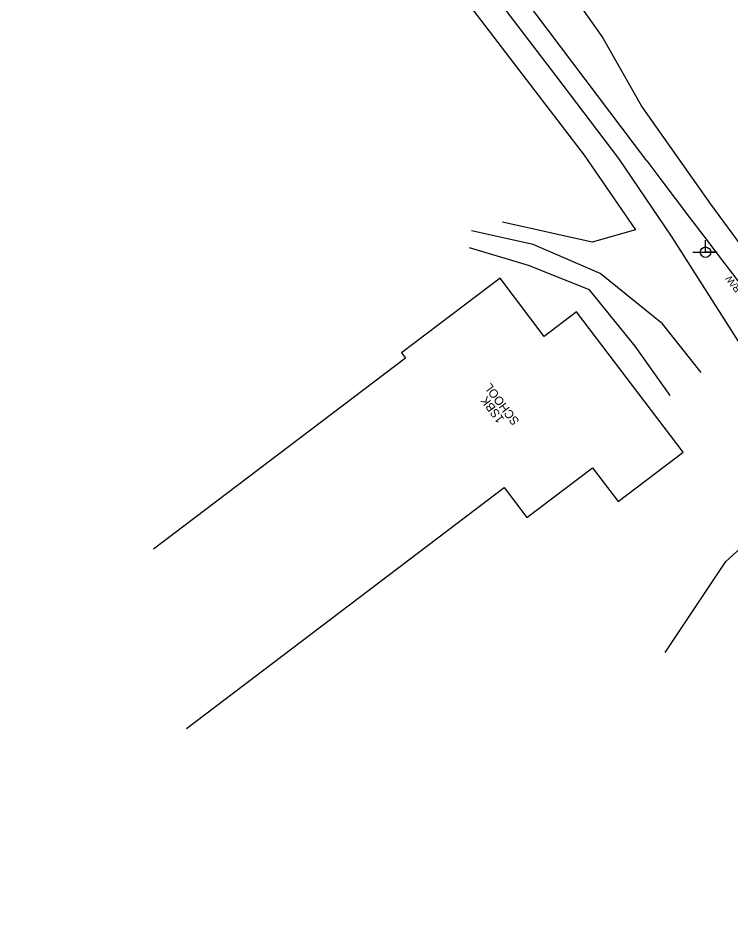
# Model space of a CAD drawing. Extents: x 1263837 to 1268319, y 770628 to 773628.
# Drawn here: x 1265545.5 to 1265875.7, y 772731.9 to 773151.3 of the extents above; entities that cross this region are included whole.
import ezdxf

# ---------------------------------------------------------------- set-up
doc = ezdxf.new("R2010")
doc.units = 0
for name, color, linetype in [('Exist Building', 7, 'Continuous'), ('Exist Building Text', 7, 'Continuous'), ('Exist Roads Soil', 7, 'Continuous'), ('Exist Utilities Gas UG Line SUE LOS B', 7, 'Continuous'), ('Exist Utilities Power Joint Use Telephone CELL', 7, 'Continuous'), ('Exist Vegetation Woods Line', 7, 'Continuous'), ('Prop Earthen Structure V Ditch Special Lateral with Rip Rap Detail CELL', 7, 'Continuous'), ('Prop Horizontal Alignment', 7, 'Continuous')]:
    doc.layers.add(name, color=color, linetype=linetype)

# ---------------------------------------------------------------- blocks, each defined once
blk = doc.blocks.new('EXIST UTILITIES POWER JOINT USE TELEPHONE')
at = {"layer": 'Exist Utilities Power Joint Use Telephone CELL'}
blk.add_line((0, 0), (0, 0), dxfattribs=at)
blk.add_lwpolyline([(-0.1188, 0), (0.108, -0.0008), (0, -0.0004), (0, 0.1125)], dxfattribs=at)
blk.add_circle((0, 0.0001), 0.049, dxfattribs=at)

msp = doc.modelspace()

# ---------------------------------------------------------------- linework, layer by layer
at = {"layer": 'Exist Building'}
for p, q in [((1265768.74, 773030.76), (1265723.08, 772996.13)), ((1265789.23, 773003.75), (1265768.74, 773030.76)), ((1265804.17, 773015.08), (1265789.23, 773003.75)), ((1265853.52, 772950.03), (1265804.17, 773015.08)), ((1265724.91, 772993.72), (1265608.21, 772905.19)), ((1265723.08, 772996.13), (1265724.91, 772993.72)), ((1265823.46, 772927.22), (1265853.52, 772950.03)), ((1265781.14, 772919.8), (1265811.57, 772942.89)), ((1265811.57, 772942.89), (1265823.46, 772927.22)), ((1265623.46, 772822.07), (1265770.61, 772933.69)), ((1265770.61, 772933.69), (1265781.14, 772919.8))]:
    msp.add_line(p, q, dxfattribs=at)
at = {"layer": 'Exist Roads Soil'}
for points in [[(1265861.85, 772986.99), (1265843.98, 773009.59), (1265815.12, 773032.96), (1265784.08, 773046.4), (1265755.54, 773052.64)], [(1265847.56, 772976.29), (1265831.4, 772999.21), (1265810.16, 773025.4), (1265781.99, 773036.63), (1265754.55, 773044.84)]]:
    msp.add_lwpolyline(points, dxfattribs=at)
at = {"layer": 'Exist Utilities Gas UG Line SUE LOS B'}
for points in [[(1265848.43, 773049.68), (1265823.79, 773086.24), (1265794.65, 773124.67), (1265761.06, 773168.65), (1265735.36, 773201.68), (1265710.2, 773236.22), (1265697.44, 773254.25), (1265675.52, 773284.85), (1265645.96, 773319.4), (1265618.05, 773328.09), (1265579.68, 773339.15), (1265557.55, 773345.75)], [(1266190.03, 772598.64), (1266172.56, 772618.95), (1266142.12, 772658.63), (1266123.67, 772683.94), (1266096.8, 772718.13), (1266076.49, 772746.81), (1266058.64, 772769.54), (1266029.6, 772809.86), (1266006.3, 772842.79), (1265964.9, 772887.19), (1265952.75, 772900.61), (1265892.03, 772981.29), (1265848.43, 773049.68)]]:
    msp.add_lwpolyline(points, dxfattribs=at)
at = {"layer": 'Exist Vegetation Woods Line'}
for points in [[(1265550.96, 773399.83), (1265565.11, 773408.97), (1265613.7, 773377.32), (1265631.2, 773323.49), (1265650.03, 773290.08), (1265668.71, 773272.08), (1265667.81, 773278.14), (1265688.59, 773247.41), (1265708.61, 773217.2), (1265728.29, 773187.53), (1265756.18, 773155.06), (1265782.86, 773120.1), (1265807.7, 773087.69), (1265831.55, 773053.2), (1265811.46, 773047.45), (1265769.82, 773056.61)], [(1265866.45, 773064.95), (1265834.29, 773110.58), (1265816.05, 773142.68), (1265793.36, 773175), (1265766.52, 773213.21), (1265746.13, 773242.14), (1265729.19, 773268.3), (1265708.07, 773294.24), (1265690.8, 773315.07), (1265676.33, 773336.34), (1265659.77, 773358.09)], [(1265845.2, 772857.24), (1265873.31, 772899.37), (1265898.05, 772921.85), (1265919.64, 772918.96), (1265940.61, 772895.89), (1265954.36, 772872.06), (1265973.36, 772865.64), (1265988, 772871.56), (1265983.87, 772888.87), (1265944.73, 772958.61), (1265866.45, 773064.95)]]:
    msp.add_lwpolyline(points, dxfattribs=at)
at = {"layer": 'Prop Horizontal Alignment'}
msp.add_line((1265836.69, 773085.15), (1265545.46, 773471.85), dxfattribs=at)
msp.add_arc((1275094.23, 780056.99), 11589.16, 216.983333, 220.45226, dxfattribs=at)

# ---------------------------------------------------------------- block references
at = {"layer": 'Exist Utilities Power Joint Use Telephone CELL', "xscale": 50, "yscale": 50}
msp.add_blockref('EXIST UTILITIES POWER JOINT USE TELEPHONE', (1265863.96, 773042.75), dxfattribs=at)

# ---------------------------------------------------------------- texts
at = {"layer": 'Exist Building Text'}
for s, p in [('SCHOOL', (1265777.89, 772964.45)), ('1SBK', (1265770.86, 772965.47))]:
    msp.add_text(s, height=4, rotation=126.9057, dxfattribs=at).set_placement(p)
at = {"layer": 'Prop Earthen Structure V Ditch Special Lateral with Rip Rap Detail CELL'}
msp.add_text('EXISTING R/W', height=3.2, rotation=127.353, dxfattribs=at).set_placement((1265893.37, 773008.87))

doc.saveas('drawing.dxf')
